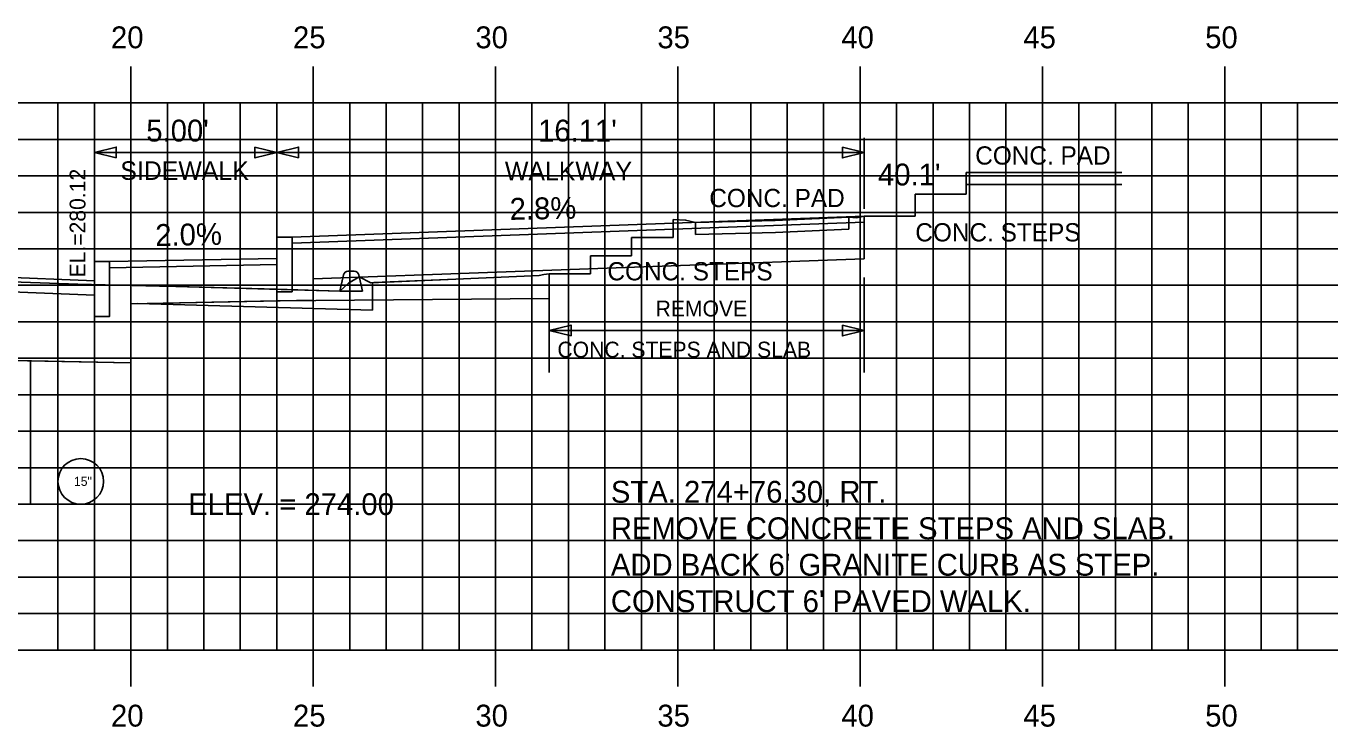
# Model space of a CAD drawing. Extents: x 853340 to 853510, y 366268 to 366378.
# Drawn here: x 853440.22 to 853475.99, y 366301.65 to 366320.87 of the extents above; entities that cross this region are included whole.
import ezdxf

# ---------------------------------------------------------------- set-up
doc = ezdxf.new("R2010")
doc.units = 0
for name, color, linetype in [('ANNOTATION', 7, 'Continuous'), ('D_Curb_Type1_Rt', 7, 'Continuous'), ('D_Roadway_Edge_TW', 7, 'Continuous'), ('D_Roadway_Sidewalks_Paved', 7, 'Continuous'), ('D_Roadway_SubGrade', 7, 'Continuous'), ('D_Text_Monospaced', 7, 'Continuous'), ('D_Text_Standard', 7, 'Continuous'), ('DIMENSIONS', 7, 'Continuous'), ('H_V ANNOTATION', 7, 'Continuous'), ('JUNK COM EXC', 7, 'Continuous'), ('junk strct exc', 7, 'Continuous'), ('MAJOR', 7, 'Continuous'), ('MINOR', 7, 'Continuous'), ('PDRAIN', 7, 'Continuous'), ('S_Curb_Type_3', 7, 'Continuous'), ('S_Roadway_Centerline', 7, 'Continuous')]:
    doc.layers.add(name, color=color, linetype=linetype)

msp = doc.modelspace()

# ---------------------------------------------------------------- linework, layer by layer
at = {"layer": 'D_Curb_Type1_Rt'}
for points in [[(853447.521, 366315.08), (853447.521, 366313.58), (853447.105, 366313.58), (853447.105, 366315.08)], [(853442.517, 366314.406), (853442.517, 366312.906), (853442.1, 366312.906), (853442.1, 366314.406)]]:
    msp.add_lwpolyline(points, close=True, dxfattribs=at)
at = {"layer": 'D_Roadway_Edge_TW'}
msp.add_line((853434.1, 366314.199), (853442.1, 366313.879), dxfattribs=at)
at = {"layer": 'D_Roadway_Sidewalks_Paved'}
for p, q in [((853447.521, 366315.08), (853463.215, 366315.653)), ((853463.213, 366314.486), (853463.213, 366315.653)), ((853447.528, 366314.914), (853463.213, 366315.487))]:
    msp.add_line(p, q, dxfattribs=at)
msp.add_lwpolyline([(853442.517, 366314.406), (853447.105, 366314.497), (853447.105, 366314.331), (853442.517, 366314.239)], close=True, dxfattribs=at)
at = {"layer": 'D_Roadway_SubGrade'}
for p, q in [((853448.1, 366313.934), (853463.213, 366314.486)), ((853448.1, 366313.352), (853448.1, 366313.934)), ((853449.725, 366313.828), (853449.725, 366313.075))]:
    msp.add_line(p, q, dxfattribs=at)
for points in [[(853443.1, 366311.63), (853434.108, 366311.81), (853434.108, 366313.81), (853442.1, 366313.49)], [(853448.1, 366313.352), (853443.1, 366313.251), (853443.1, 366311.63)], [(853443.292, 366313.255), (853449.725, 366313.075)]]:
    msp.add_lwpolyline(points, dxfattribs=at)
at = {"layer": 'D_Text_Standard'}
msp.add_lwpolyline([(853443.1, 366307.757), (853443.31, 366307.757), (853443.99, 366307.757)], dxfattribs=at)
at = {"layer": 'DIMENSIONS'}
for p, q in [((853442.1, 366313.49), (853442.1, 366317.8)), ((853447.101, 366316.319), (853447.101, 366317.8)), ((853447.105, 366314.837), (853447.105, 366317.8)), ((853463.213, 366315.853), (853463.213, 366317.8)), ((853442.1, 366317.4), (853447.101, 366317.4)), ((853463.213, 366317.4), (853447.101, 366317.4)), ((853454.571, 366311.365), (853454.571, 366313.971)), ((853463.213, 366313.971), (853463.213, 366311.365)), ((853463.213, 366312.519), (853454.571, 366312.519))]:
    msp.add_line(p, q, dxfattribs=at)
for points in [[(853442.7, 366317.25), (853442.1, 366317.4), (853442.7, 366317.55)], [(853446.501, 366317.55), (853447.101, 366317.4), (853446.501, 366317.25)], [(853447.701, 366317.25), (853447.101, 366317.4), (853447.701, 366317.55)], [(853462.613, 366317.55), (853463.213, 366317.4), (853462.613, 366317.25)], [(853455.171, 366312.369), (853454.571, 366312.519), (853455.171, 366312.669)], [(853462.613, 366312.669), (853463.213, 366312.519), (853462.613, 366312.369)]]:
    msp.add_lwpolyline(points, close=True, dxfattribs=at)
at = {"layer": 'JUNK COM EXC'}
for points in [[(853403.1, 366313.783), (853403.1, 366311.792), (853412.108, 366311.972), (853423.108, 366312.03), (853443.1, 366311.63), (853443.1, 366313.251), (853447.105, 366313.332), (853447.105, 366313.648), (853444.01, 366313.735), (853443.885, 366313.73), (853441.643, 366313.789), (853435.938, 366313.988), (853425.848, 366314.256), (853423.1, 366314.352), (853417.701, 366314.327), (853411.542, 366314.212), (853408.292, 366314.075), (853404.573, 366313.84), (853403.1, 366313.783)], [(853447.105, 366313.648), (853447.105, 366313.33), (853454.571, 366313.393), (853454.571, 366314.069), (853454.426, 366314.05), (853454.293, 366314.022), (853452.013, 366313.927), (853449.683, 366313.823), (853449.359, 366313.991), (853449.069, 366313.813), (853448.826, 366313.6), (853447.105, 366313.648)]]:
    msp.add_lwpolyline(points, dxfattribs=at)
at = {"layer": 'junk strct exc'}
msp.add_lwpolyline([(853440.35, 366311.685), (853440.35, 366307.757), (853443.1, 366307.757), (853443.1, 366311.63)], close=True, dxfattribs=at)
at = {"layer": 'MAJOR'}
for p, q in [((853443.1, 366319.759), (853443.1, 366318.757)), ((853448.1, 366319.759), (853448.1, 366318.757)), ((853453.1, 366319.759), (853453.1, 366318.757)), ((853458.1, 366319.759), (853458.1, 366318.757)), ((853463.1, 366319.759), (853463.1, 366318.757)), ((853468.1, 366319.759), (853468.1, 366318.757)), ((853473.1, 366319.759), (853473.1, 366318.757)), ((853353.1, 366318.757), (853493.1, 366318.757)), ((853353.1, 366318.757), (853493.1, 366318.757)), ((853443.1, 366303.757), (853443.1, 366318.757)), ((853448.1, 366303.757), (853448.1, 366318.757)), ((853453.1, 366303.757), (853453.1, 366318.757)), ((853458.1, 366303.757), (853458.1, 366318.757)), ((853463.1, 366303.757), (853463.1, 366318.757)), ((853468.1, 366303.757), (853468.1, 366318.757)), ((853473.1, 366303.757), (853473.1, 366318.757)), ((853353.1, 366313.757), (853493.1, 366313.757)), ((853353.1, 366308.757), (853493.1, 366308.757)), ((853353.1, 366303.757), (853493.1, 366303.757)), ((853443.1, 366302.755), (853443.1, 366303.757)), ((853448.1, 366302.755), (853448.1, 366303.757)), ((853453.1, 366302.755), (853453.1, 366303.757)), ((853458.1, 366302.755), (853458.1, 366303.757)), ((853463.1, 366302.755), (853463.1, 366303.757)), ((853468.1, 366302.755), (853468.1, 366303.757)), ((853473.1, 366302.755), (853473.1, 366303.757))]:
    msp.add_line(p, q, dxfattribs=at)
at = {"layer": 'MINOR'}
for p, q in [((853441.1, 366303.757), (853441.1, 366318.757)), ((853442.1, 366303.757), (853442.1, 366318.757)), ((853444.1, 366303.757), (853444.1, 366318.757)), ((853445.1, 366303.757), (853445.1, 366318.757)), ((853446.1, 366303.757), (853446.1, 366318.757)), ((853447.1, 366303.757), (853447.1, 366318.757)), ((853449.1, 366303.757), (853449.1, 366318.757)), ((853450.1, 366303.757), (853450.1, 366318.757)), ((853451.1, 366303.757), (853451.1, 366318.757)), ((853452.1, 366303.757), (853452.1, 366318.757)), ((853454.1, 366303.757), (853454.1, 366318.757)), ((853455.1, 366303.757), (853455.1, 366318.757)), ((853456.1, 366303.757), (853456.1, 366318.757)), ((853457.1, 366303.757), (853457.1, 366318.757)), ((853459.1, 366303.757), (853459.1, 366318.757)), ((853460.1, 366303.757), (853460.1, 366318.757)), ((853461.1, 366303.757), (853461.1, 366318.757)), ((853462.1, 366303.757), (853462.1, 366318.757)), ((853464.1, 366303.757), (853464.1, 366318.757)), ((853465.1, 366303.757), (853465.1, 366318.757)), ((853466.1, 366303.757), (853466.1, 366318.757)), ((853467.1, 366303.757), (853467.1, 366318.757)), ((853469.1, 366303.757), (853469.1, 366318.757)), ((853470.1, 366303.757), (853470.1, 366318.757)), ((853471.1, 366303.757), (853471.1, 366318.757)), ((853472.1, 366303.757), (853472.1, 366318.757)), ((853474.1, 366303.757), (853474.1, 366318.757)), ((853475.1, 366303.757), (853475.1, 366318.757)), ((853353.1, 366317.757), (853493.1, 366317.757)), ((853353.1, 366316.757), (853493.1, 366316.757)), ((853353.1, 366315.757), (853493.1, 366315.757)), ((853353.1, 366314.757), (853493.1, 366314.757)), ((853353.1, 366312.757), (853493.1, 366312.757)), ((853353.1, 366311.757), (853493.1, 366311.757)), ((853353.1, 366310.757), (853493.1, 366310.757)), ((853353.1, 366309.757), (853493.1, 366309.757)), ((853353.1, 366307.757), (853493.1, 366307.757)), ((853353.1, 366306.757), (853493.1, 366306.757)), ((853353.1, 366305.757), (853493.1, 366305.757)), ((853353.1, 366304.757), (853493.1, 366304.757))]:
    msp.add_line(p, q, dxfattribs=at)
at = {"layer": 'PDRAIN'}
msp.add_lwpolyline([(853440.35, 366311.685), (853440.35, 366307.757), (853443.1, 366307.757), (853443.1, 366311.63)], dxfattribs=at)
msp.add_circle((853441.725, 366308.382), 0.625, dxfattribs=at)
at = {"layer": 'S_Curb_Type_3'}
for points in [[(853449.349, 366314.045), (853449.451, 366313.6), (853448.826, 366313.6), (853448.929, 366314.045)], [(853449.051, 366314.142), (853449.227, 366314.142)]]:
    msp.add_lwpolyline(points, dxfattribs=at)
for centre, start, end in [((853449.051, 366314.017), 90, 167.0054), ((853449.227, 366314.017), 12.9946, 90)]:
    msp.add_arc(centre, 0.125, start, end, dxfattribs=at)
at = {"layer": 'S_Roadway_Centerline'}
for p, q in [((853466.006, 366316.253), (853466.006, 366316.853)), ((853466.006, 366316.853), (853470.274, 366316.853)), ((853466.006, 366316.52), (853470.274, 366316.52)), ((853464.606, 366315.653), (853464.606, 366316.253)), ((853464.606, 366316.253), (853466.006, 366316.253)), ((853463.215, 366315.653), (853464.606, 366315.653)), ((853457.969, 366315.069), (853457.969, 366315.562)), ((853458.588, 366315.15), (853458.588, 366315.483)), ((853462.788, 366315.295), (853462.788, 366315.628)), ((853456.831, 366315.069), (853457.969, 366315.069)), ((853456.831, 366314.569), (853456.831, 366315.069)), ((853455.701, 366314.569), (853456.831, 366314.569)), ((853455.701, 366314.069), (853455.701, 366314.569)), ((853454.571, 366314.069), (853455.701, 366314.069))]:
    msp.add_line(p, q, dxfattribs=at)
for points in [[(853457.969, 366315.562), (853458.311, 366315.545), (853458.588, 366315.483), (853460.769, 366315.536), (853462.788, 366315.628), (853462.999, 366315.61), (853463.215, 366315.653)], [(853458.588, 366315.15), (853460.78, 366315.203), (853462.788, 366315.295)], [(853390.695, 366312.884), (853396.582, 366312.962), (853402.362, 366313.754), (853404.573, 366313.84), (853408.292, 366314.075), (853411.542, 366314.212), (853417.701, 366314.327), (853423.1, 366314.352), (853425.848, 366314.256), (853435.938, 366313.988), (853441.643, 366313.789), (853443.885, 366313.73), (853444.01, 366313.735), (853448.826, 366313.6), (853449.069, 366313.813), (853449.359, 366313.991), (853449.683, 366313.823), (853449.767, 366313.833), (853452.013, 366313.927), (853454.293, 366314.022), (853454.426, 366314.05), (853454.571, 366314.069)]]:
    msp.add_lwpolyline(points, dxfattribs=at)

# ---------------------------------------------------------------- texts
at = {"layer": 'ANNOTATION'}
for s, p in [('2.8%', (853453.493, 366315.55)), ('2.0%', (853443.773, 366314.832))]:
    msp.add_text(s, height=0.6, rotation=1.1363, dxfattribs=at).set_placement(p)
for s, p in [('STA. 274+76.30, RT.', (853456.264, 366307.795)), ('REMOVE CONCRETE STEPS AND SLAB.', (853456.264, 366306.795)), ("ADD BACK 6' GRANITE CURB AS STEP.", (853456.264, 366305.795)), ("CONSTRUCT 6' PAVED WALK.", (853456.264, 366304.795))]:
    msp.add_text(s, height=0.6, dxfattribs=at).set_placement(p)
at = {"layer": 'D_Text_Monospaced'}
for s, height, p in [('CONC. PAD', 0.5, (853466.257, 366317.068)), ('CONC. PAD', 0.5, (853458.963, 366315.902)), ('CONC. STEPS', 0.49998, (853464.614, 366314.961)), ('CONC. STEPS', 0.49998, (853456.169, 366313.893))]:
    msp.add_text(s, height=height, dxfattribs=at).set_placement(p)
at = {"layer": 'D_Text_Standard'}
for s, p in [("40.1'", (853463.59, 366316.495)), ('ELEV. = 274.00', (853444.67, 366307.457))]:
    msp.add_text(s, height=0.6, dxfattribs=at).set_placement(p)
msp.add_text(' EL.=280.12', height=0.4335, rotation=90, dxfattribs=at).set_placement((853441.854, 366313.81))
at = {"layer": 'DIMENSIONS'}
for s, height, p in [("5.00'", 0.6, (853443.522, 366317.7)), ("16.11'", 0.6, (853454.266, 366317.7)), ('SIDEWALK', 0.51, (853442.81, 366316.648)), ('WALKWAY', 0.51, (853453.358, 366316.634)), ('REMOVE', 0.4335, (853457.49, 366312.904)), ('CONC. STEPS AND SLAB', 0.4335, (853454.798, 366311.778))]:
    msp.add_text(s, height=height, dxfattribs=at).set_placement(p)
at = {"layer": 'H_V ANNOTATION'}
for s, p in [('20', (853442.554, 366320.257)), ('25', (853447.546, 366320.257)), ('30', (853452.548, 366320.257)), ('35', (853457.54, 366320.257)), ('40', (853462.586, 366320.257)), ('45', (853467.578, 366320.257)), ('50', (853472.564, 366320.257)), ('20', (853442.554, 366301.657)), ('25', (853447.546, 366301.657)), ('30', (853452.548, 366301.657)), ('35', (853457.54, 366301.657)), ('40', (853462.586, 366301.657)), ('45', (853467.578, 366301.657)), ('50', (853472.564, 366301.657))]:
    msp.add_text(s, height=0.6, dxfattribs=at).set_placement(p)
at = {"layer": 'PDRAIN'}
msp.add_text('15"', height=0.25, dxfattribs=at).set_placement((853441.538, 366308.257))

doc.saveas('drawing.dxf')
